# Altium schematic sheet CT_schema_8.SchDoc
size 371 x 245 mm
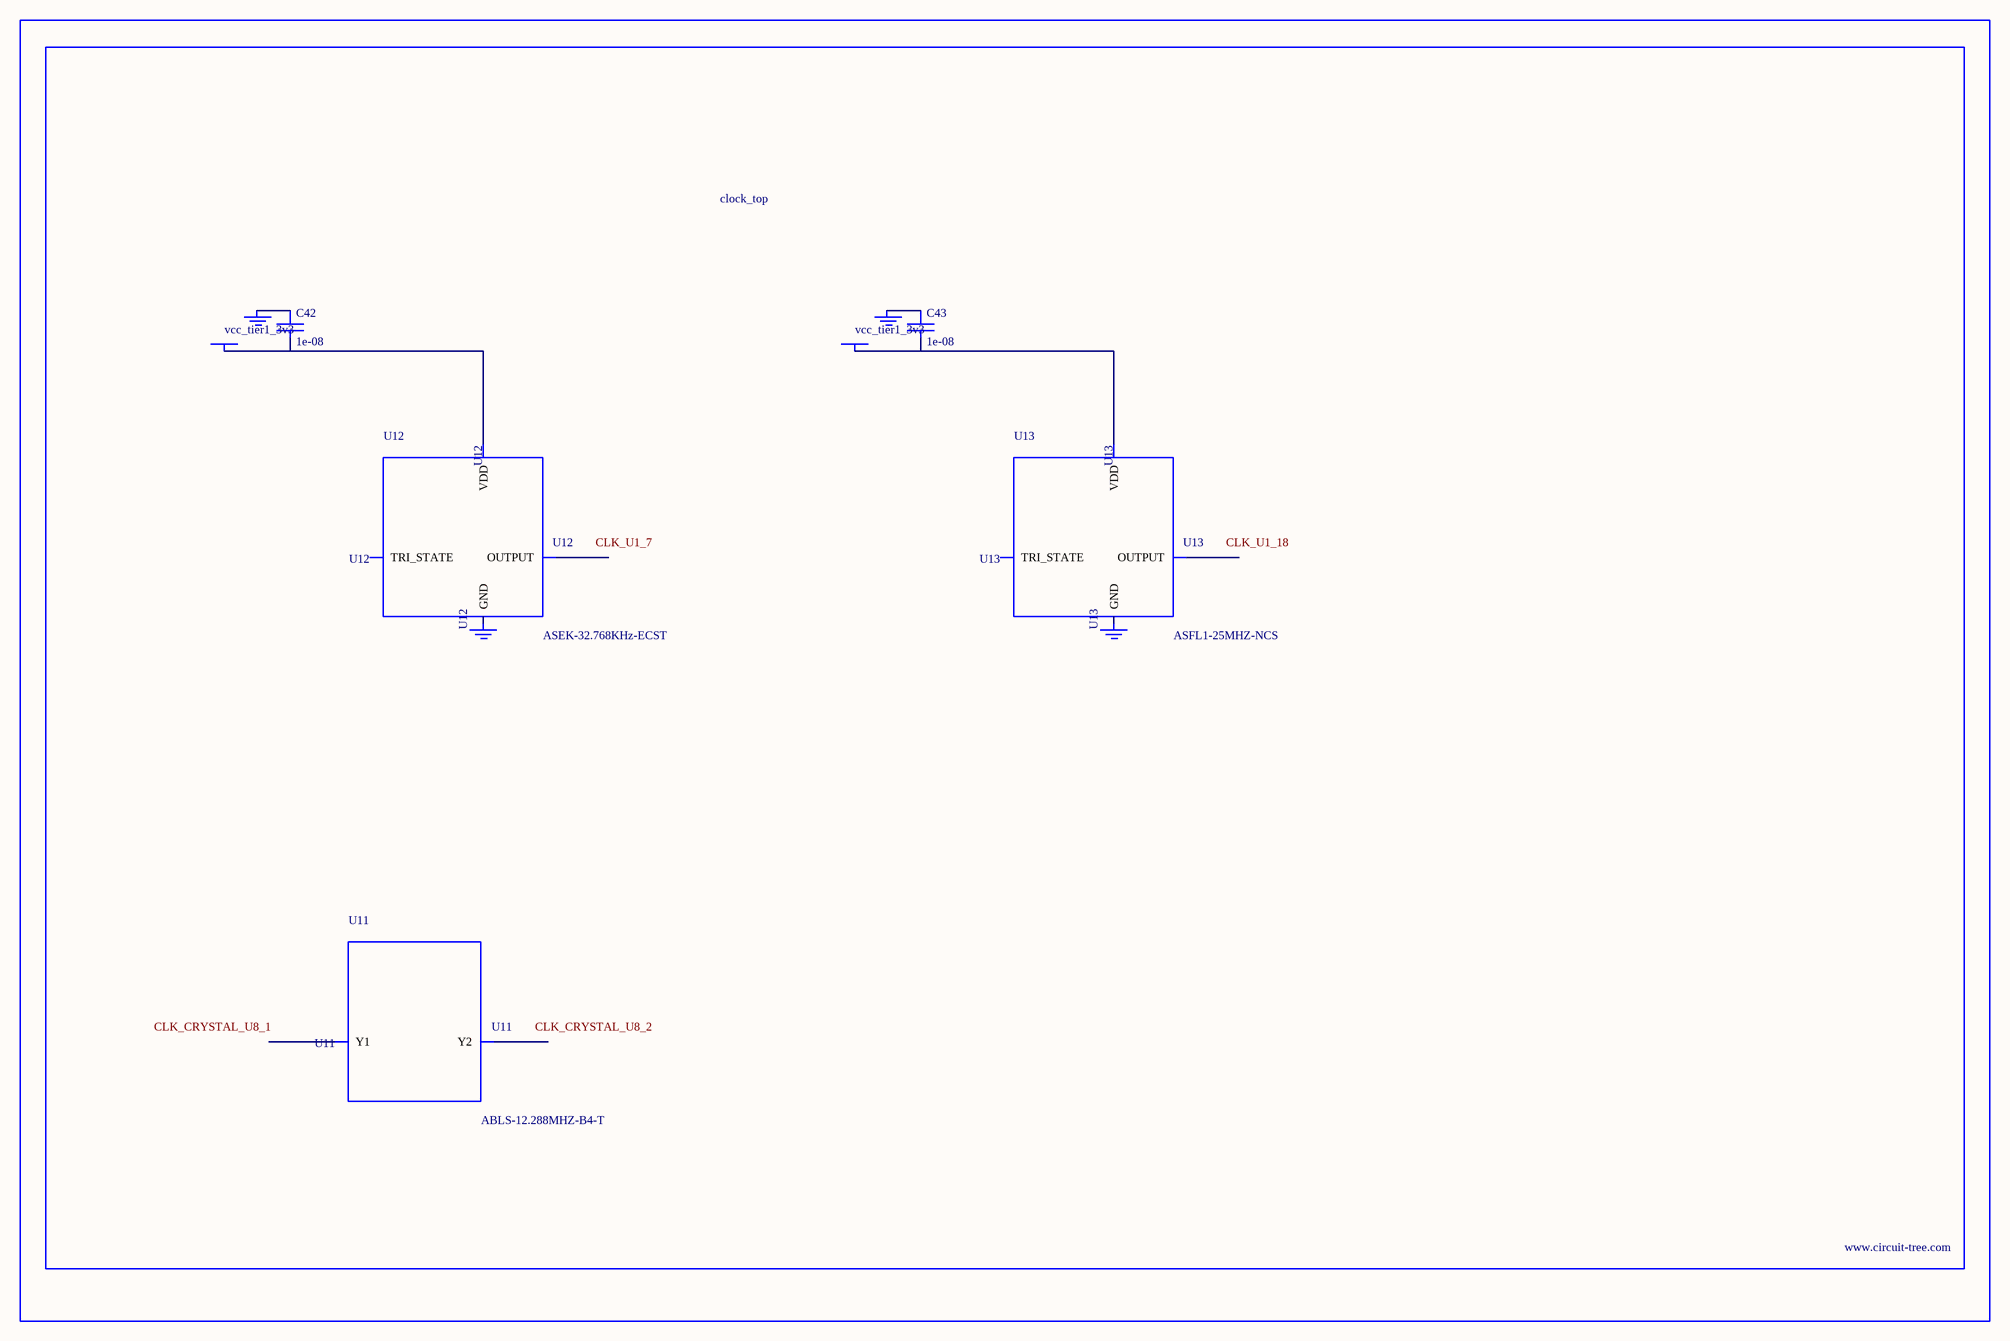
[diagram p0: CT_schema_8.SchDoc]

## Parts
BORDER7  (no value)
C42  1e-08  [C0402]
C43  1e-08  [C0402]
GND_INSTANCE_7_0  (no value)
GND_INSTANCE_7_1  (no value)
GND_INSTANCE_7_2  (no value)
GND_INSTANCE_7_3  (no value)
POWER_INSTANCE_7_0  vcc_tier1_3v3
POWER_INSTANCE_7_1  vcc_tier1_3v3
U11  ABLS-12.288MHZ-B4-T  [ABLS-12.288MHZ-B4-T]
U12  ASEK-32.768KHz-ECST  [ASEK]
U13  ASFL1-25MHZ-NCS  [ASFL1]

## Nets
NetC42_1: C42.1 GND_INSTANCE_7_0.0(GND)
NetC42_2: C42.2 POWER_INSTANCE_7_0.0(PWR) U12.4(VDD)
NetC43_1: C43.1 GND_INSTANCE_7_2.0(GND)
NetC43_2: C43.2 POWER_INSTANCE_7_1.0(PWR) U13.4(VDD)

Not connected (* = marked no-connect by the designer): GND_INSTANCE_7_1 0(GND); GND_INSTANCE_7_3 0(GND); U11 1(Y1) 2(Y2); U12 1(TRI_STATE) 2(GND) 3(OUTPUT); U13 1(TRI_STATE) 2(GND) 3(OUTPUT)

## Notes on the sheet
- Labels drawn without touching a wire or pin: CLK_CRYSTAL_U8_1, CLK_CRYSTAL_U8_2, CLK_U1_7, CLK_U1_18

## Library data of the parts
BORDER7 = BORDER_PAGE7
C42 C43 = C0402C103K3RAC
GND_INSTANCE_7_0-GND_INSTANCE_7_3 = GND
POWER_INSTANCE_7_0 POWER_INSTANCE_7_1 = PWR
